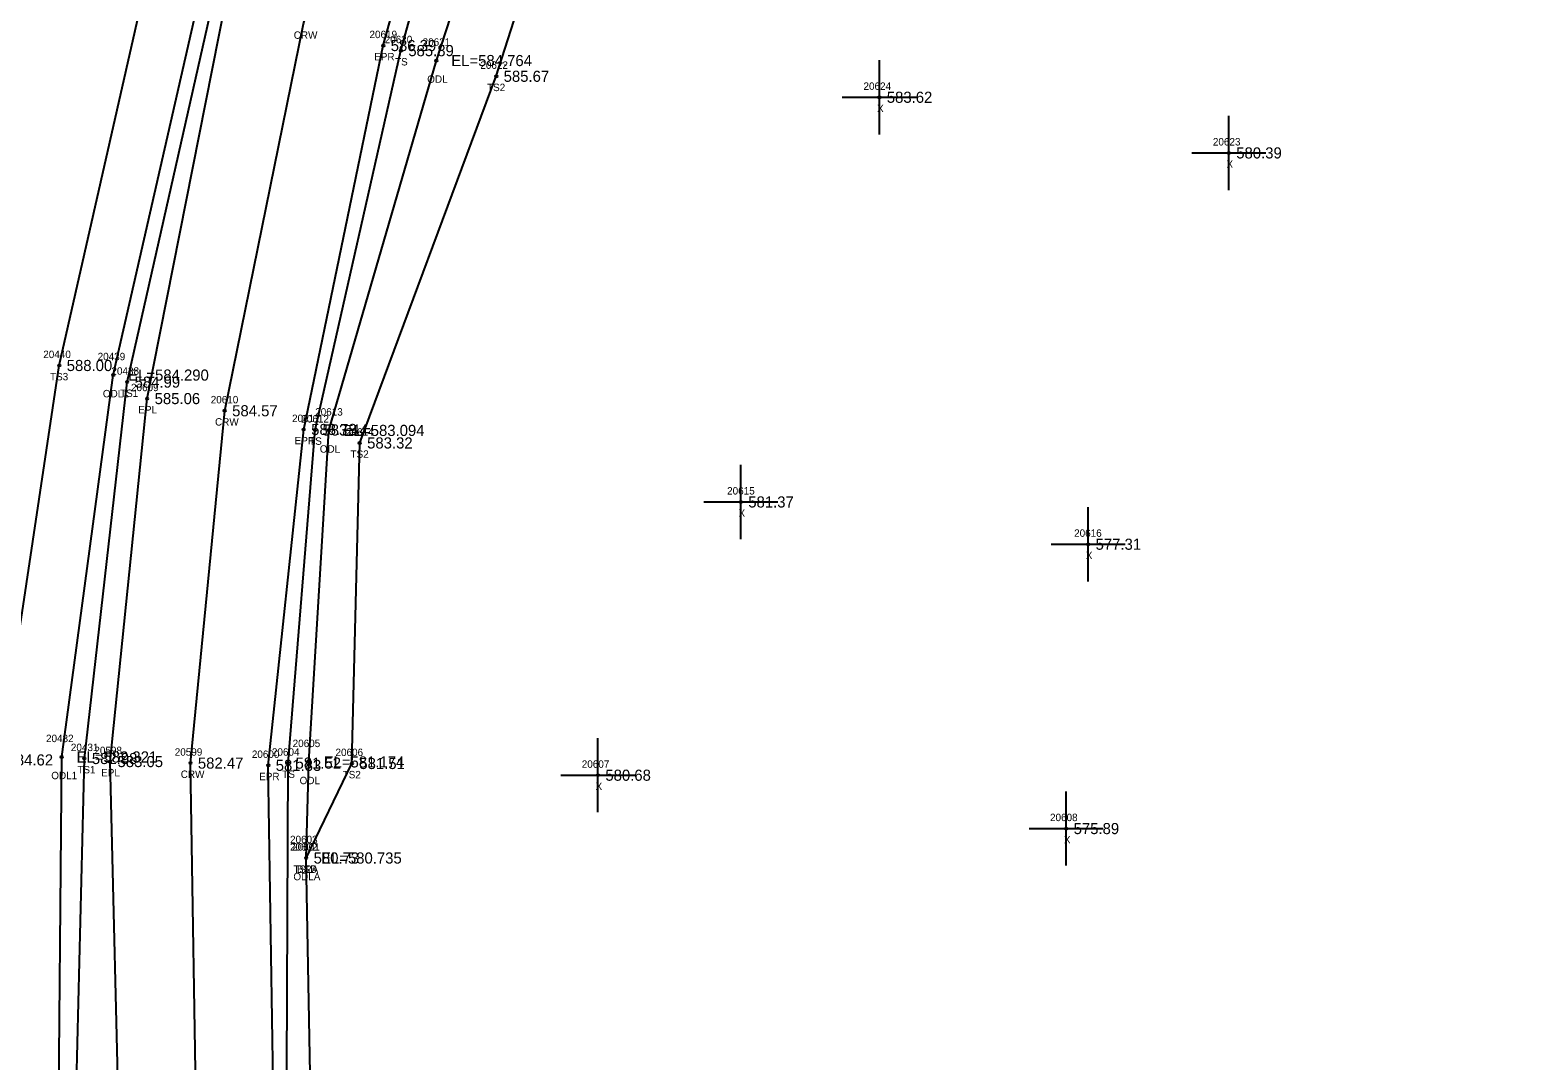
# Model space of a CAD drawing. Extents: x 1695443 to 1696344, y 1087542 to 1090645.
# Drawn here: x 1695695.8 to 1695899, y 1089395 to 1089533.9 of the extents above; entities that cross this region are included whole.
import ezdxf

# ---------------------------------------------------------------- set-up
doc = ezdxf.new("R2010")
doc.units = 0
for name, color, linetype in [('RD_DTM_BkLn1', 7, 'Continuous'), ('RD_DTM_BkLn2', 7, 'Continuous'), ('RD_DTM_BkLn_txCode', 7, 'Continuous'), ('RD_EX_H2O', 7, 'Continuous'), ('RD_EX_H2O_txCode', 7, 'Continuous'), ('RD_EX_Misc', 7, 'Continuous'), ('RD_EX_Misc_txCode', 7, 'Continuous'), ('RD_EX_Road', 7, 'Continuous'), ('RD_EX_Road_txCode', 7, 'Continuous'), ('RD_EX_TX_H2O_ELEV', 7, 'Continuous'), ('RD_EX_TX_Misc_ELEV', 7, 'Continuous'), ('RD_EX_TX_Road_ELEV', 7, 'Continuous'), ('RD_HC_Survey_ELEV', 7, 'Continuous'), ('RD_HC_Survey_txCode', 7, 'Continuous'), ('RD_SMD_Locator', 7, 'Continuous')]:
    doc.layers.add(name, color=color, linetype=linetype)

msp = doc.modelspace()

# ---------------------------------------------------------------- linework, layer by layer
at = {"layer": 'RD_DTM_BkLn1'}
msp.add_lwpolyline([(1695813.78, 1089148.1), (1695785.55, 1089189.03), (1695758.89, 1089235.87), (1695740.64, 1089279.02), (1695725.17, 1089334.02), (1695718.27, 1089382.65), (1695717.41, 1089435.13), (1695722.03, 1089482.62), (1695732.64, 1089534.75), (1695759.85, 1089631.43), (1695787.11, 1089727.89), (1695798.89, 1089774.41), (1695810.31, 1089824.5), (1695818.49, 1089870.61), (1695825.85, 1089922.33), (1695831.69, 1089976.57), (1695835.49, 1090019.27), (1695844.06, 1090117.91), (1695852.56, 1090215.73), (1695861.78, 1090313.02), (1695870.8, 1090411.68), (1695879.44, 1090510.15), (1695888.04, 1090606.94)], dxfattribs=at)
at = {"layer": 'RD_DTM_BkLn2'}
for points in [[(1695696.87, 1089328.65), (1695685.13, 1089358.98), (1695692.41, 1089382.13), (1695691.76, 1089435.56), (1695699.73, 1089488.72), (1695712.17, 1089543.62), (1695742.06, 1089638.06), (1695765.36, 1089733.76), (1695777.86, 1089780.36), (1695790.39, 1089828.61), (1695799.49, 1089874.59), (1695809.45, 1089923.14)], [(1695802.49, 1089139.56), (1695797.31, 1089139.87), (1695796.55, 1089145.92), (1695767.85, 1089172.77), (1695752.08, 1089198.99), (1695743.04, 1089224.25), (1695723.93, 1089271.63), (1695706.46, 1089330), (1695701.78, 1089380.95), (1695703.12, 1089435.75), (1695708.88, 1089486.48), (1695720.72, 1089539.1), (1695747.1, 1089636.56), (1695773.41, 1089730.59), (1695786.04, 1089777.66), (1695796.55, 1089826.24), (1695804.53, 1089873.75), (1695809.45, 1089923.14)], [(1695824.1, 1089156.08), (1695822.08, 1089163.12), (1695799.61, 1089199.21), (1695776.92, 1089245.16), (1695754.8, 1089284.38), (1695737.73, 1089336.15), (1695730.34, 1089383.59), (1695730.57, 1089435.13), (1695734.2, 1089480.03), (1695745.77, 1089531.16), (1695772.55, 1089627.13), (1695801.84, 1089724.13), (1695813.32, 1089771.8), (1695823.97, 1089812.55), (1695828.38, 1089814.06), (1695832.18, 1089812.32)], [(1695733.01, 1089422.34), (1695739.17, 1089435.08), (1695740.22, 1089478.28), (1695758.62, 1089527.7), (1695775.29, 1089579.66), (1695790.54, 1089625.04), (1695813.11, 1089721.69), (1695822.77, 1089769.83), (1695832.18, 1089812.32)], [(1695806.13, 1089128.88), (1695831.97, 1089151.08), (1695836.66, 1089166.87), (1695814.23, 1089210.18), (1695792.32, 1089250.79), (1695765.95, 1089289.34), (1695750.81, 1089305.62), (1695742.03, 1089337.12), (1695733.74, 1089383.59), (1695733.01, 1089422.34)]]:
    msp.add_lwpolyline(points, dxfattribs=at)
at = {"layer": 'RD_EX_H2O'}
for points in [[(1695696.87, 1089328.65), (1695699.57, 1089380.43), (1695700.06, 1089435.96), (1695707.01, 1089487.43), (1695718.96, 1089539.87), (1695744.93, 1089637.33), (1695772.06, 1089731.31), (1695783.6, 1089778.47), (1695794.38, 1089827.05), (1695802.7, 1089874.04), (1695809.45, 1089923.14)], [(1695733.01, 1089422.34), (1695733.36, 1089435.29), (1695736.08, 1089479.97), (1695750.56, 1089529.82), (1695767.47, 1089581.7), (1695784.92, 1089622.19), (1695808.14, 1089722.97), (1695818.49, 1089770.57), (1695827.73, 1089811.05)]]:
    msp.add_lwpolyline(points, dxfattribs=at)
at = {"layer": 'RD_EX_Misc'}
for p, q in [((1695810.26, 1089519.87), (1695810.26, 1089529.87)), ((1695805.26, 1089524.87), (1695815.26, 1089524.87)), ((1695857.36, 1089512.37), (1695857.36, 1089522.37)), ((1695852.36, 1089517.37), (1695862.36, 1089517.37)), ((1695791.59, 1089465.33), (1695791.59, 1089475.33)), ((1695786.59, 1089470.33), (1695796.59, 1089470.33)), ((1695838.4, 1089459.63), (1695838.4, 1089469.63)), ((1695833.4, 1089464.63), (1695843.4, 1089464.63)), ((1695772.33, 1089428.5), (1695772.33, 1089438.5)), ((1695767.33, 1089433.5), (1695777.33, 1089433.5)), ((1695835.44, 1089421.31), (1695835.44, 1089431.31)), ((1695830.44, 1089426.31), (1695840.44, 1089426.31))]:
    msp.add_line(p, q, dxfattribs=at)
at = {"layer": 'RD_EX_Road'}
for points in [[(1695813.78, 1089148.1), (1695805.56, 1089142.08), (1695776.44, 1089183.94), (1695749.27, 1089231.88), (1695730.49, 1089275.72), (1695714.87, 1089332.12), (1695707.87, 1089381.72), (1695706.58, 1089435.34), (1695711.58, 1089484.26), (1695722.15, 1089537.59), (1695749.04, 1089634.88), (1695776.11, 1089730.43), (1695788.13, 1089777.42), (1695798.89, 1089826.76), (1695807.1, 1089870.03), (1695814.71, 1089923.3), (1695820.51, 1089978.16), (1695824.04, 1090019.79), (1695832.76, 1090119.06), (1695841.25, 1090216.76), (1695850.36, 1090314.41), (1695859.24, 1090411.82), (1695868.09, 1090511.63), (1695876.75, 1090608.38)], [(1695728.69, 1089383.6), (1695727.9, 1089434.83), (1695732.68, 1089480.1), (1695743.4, 1089531.84), (1695770.35, 1089628.36), (1695797.63, 1089725.22), (1695809.49, 1089772.37), (1695818.34, 1089811.57), (1695820.65, 1089823.41), (1695822.99, 1089835.26), (1695829.18, 1089869.37), (1695836.32, 1089920.97), (1695842.44, 1089975.46), (1695846.49, 1090018.55), (1695849.32, 1090055.39), (1695850.91, 1090072.92), (1695855.09, 1090117.49), (1695863.53, 1090214.93), (1695872.56, 1090312.44), (1695881.69, 1090410.78), (1695890.45, 1090509.3), (1695899.01, 1090605.4)]]:
    msp.add_lwpolyline(points, dxfattribs=at)
at = {"layer": 'RD_SMD_Locator'}
for centre in [(1695743.4, 1089531.84), (1695745.77, 1089531.16), (1695750.56, 1089529.82), (1695758.62, 1089527.7), (1695810.26, 1089524.87), (1695857.36, 1089517.37), (1695699.73, 1089488.72), (1695707.01, 1089487.43), (1695708.88, 1089486.48), (1695711.58, 1089484.26), (1695722.03, 1089482.62), (1695732.68, 1089480.1), (1695734.2, 1089480.03), (1695736.08, 1089479.97), (1695740.22, 1089478.28), (1695791.59, 1089470.33), (1695838.4, 1089464.63), (1695700.06, 1089435.96), (1695703.12, 1089435.75), (1695706.58, 1089435.34), (1695717.41, 1089435.13), (1695727.9, 1089434.83), (1695730.57, 1089435.13), (1695733.36, 1089435.29), (1695739.17, 1089435.08), (1695772.33, 1089433.5), (1695835.44, 1089426.31), (1695733.01, 1089422.34), (1695733.01, 1089422.34), (1695733.01, 1089422.34)]:
    msp.add_circle(centre, 0.15, dxfattribs=at)

# ---------------------------------------------------------------- texts
at = {"layer": 'RD_DTM_BkLn_txCode'}
for s, p in [('20620', (1695743.59, 1089532.16)), ('TS', (1695744.98, 1089529.16)), ('20622', (1695756.48, 1089528.7)), ('TS2', (1695757.38, 1089525.7)), ('20440', (1695697.57, 1089489.72)), ('TS3', (1695698.48, 1089486.72)), ('20438', (1695706.76, 1089487.48)), ('TS1', (1695707.92, 1089484.48)), ('20612', (1695732.35, 1089481.03)), ('20614', (1695738.37, 1089479.28)), ('TS', (1695733.41, 1089478.03)), ('TS2', (1695738.98, 1089476.28)), ('20431', (1695701.29, 1089436.75)), ('20604', (1695728.39, 1089436.13)), ('20606', (1695736.96, 1089436.08)), ('TS1', (1695702.16, 1089433.75)), ('TS', (1695729.78, 1089433.13)), ('TS2', (1695737.92, 1089433.08)), ('20602', (1695730.83, 1089423.34)), ('20601', (1695731.11, 1089423.34)), ('TS2A', (1695731.28, 1089420.34)), ('BSB', (1695731.76, 1089420.34))]:
    msp.add_text(s, height=1, dxfattribs=at).set_placement(p)
at = {"layer": 'RD_EX_H2O_txCode'}
for s, p in [('20621', (1695748.7, 1089531.82)), ('ODL', (1695749.32, 1089526.82)), ('20439', (1695704.9, 1089489.43)), ('ODL1', (1695705.6, 1089484.43)), ('20613', (1695734.22, 1089481.97)), ('ODL', (1695734.84, 1089476.97)), ('20432', (1695697.94, 1089437.96)), ('20605', (1695731.18, 1089437.29)), ('ODL1', (1695698.65, 1089432.96)), ('ODL', (1695732.12, 1089432.29)), ('20603', (1695730.83, 1089424.34)), ('ODLA', (1695731.28, 1089419.34))]:
    msp.add_text(s, height=1, dxfattribs=at).set_placement(p)
at = {"layer": 'RD_EX_Misc_txCode'}
for s, p in [('20624', (1695808.12, 1089525.87)), ('X', (1695809.95, 1089522.87)), ('20623', (1695855.21, 1089518.37)), ('X', (1695857.04, 1089515.37)), ('20615', (1695789.74, 1089471.33)), ('X', (1695791.28, 1089468.33)), ('20616', (1695836.51, 1089465.63)), ('X', (1695838.08, 1089462.63)), ('20607', (1695770.15, 1089434.5)), ('X', (1695772.01, 1089431.5)), ('20608', (1695833.26, 1089427.31)), ('X', (1695835.13, 1089424.31))]:
    msp.add_text(s, height=1, dxfattribs=at).set_placement(p)
at = {"layer": 'RD_EX_Road_txCode'}
for s, p in [('20619', (1695741.54, 1089532.84)), ('EPR', (1695742.17, 1089529.84)), ('20609', (1695709.4, 1089485.26)), ('EPL', (1695710.38, 1089482.26)), ('20611', (1695731.1, 1089481.1)), ('EPR', (1695731.45, 1089478.1)), ('20598', (1695704.46, 1089436.34)), ('20600', (1695725.68, 1089435.83)), ('EPL', (1695705.37, 1089433.34)), ('EPR', (1695726.67, 1089432.83))]:
    msp.add_text(s, height=1, dxfattribs=at).set_placement(p)
at = {"layer": 'RD_EX_TX_H2O_ELEV'}
for s, p in [('EL=584.764', (1695752.56, 1089529.07)), ('EL=584.290', (1695709.01, 1089486.68)), ('EL=583.094', (1695738.08, 1089479.22)), ('EL=582.321', (1695702.06, 1089435.21)), ('EL=581.174', (1695735.36, 1089434.54)), ('EL=580.735', (1695735.01, 1089421.59))]:
    msp.add_text(s, height=1.5, dxfattribs=at).set_placement(p)
at = {"layer": 'RD_EX_TX_Misc_ELEV'}
for s, p in [('585.89', (1695746.77, 1089530.41)), ('585.67', (1695759.62, 1089526.95)), ('583.62', (1695811.26, 1089524.12)), ('580.39', (1695858.36, 1089516.62)), ('588.00', (1695700.73, 1089487.97)), ('584.99', (1695709.88, 1089485.73)), ('583.44', (1695735.2, 1089479.28)), ('583.32', (1695741.22, 1089477.53)), ('581.37', (1695792.59, 1089469.58)), ('577.31', (1695839.4, 1089463.88)), ('584.62', (1695692.76, 1089434.81)), ('582.98', (1695704.12, 1089435)), ('581.52', (1695731.57, 1089434.38)), ('581.51', (1695740.17, 1089434.33)), ('580.68', (1695773.33, 1089432.75)), ('575.89', (1695836.44, 1089425.56)), ('580.73', (1695734.01, 1089421.59)), ('580.73', (1695734.01, 1089421.59))]:
    msp.add_text(s, height=1.5, dxfattribs=at).set_placement(p)
at = {"layer": 'RD_EX_TX_Road_ELEV'}
for s, p in [('586.39', (1695744.4, 1089531.09)), ('585.06', (1695712.58, 1089483.51)), ('583.78', (1695733.68, 1089479.35)), ('583.05', (1695707.58, 1089434.59)), ('581.83', (1695728.9, 1089434.08))]:
    msp.add_text(s, height=1.5, dxfattribs=at).set_placement(p)
at = {"layer": 'RD_HC_Survey_ELEV'}
for s, p in [('584.57', (1695723.03, 1089481.87)), ('582.47', (1695718.41, 1089434.38))]:
    msp.add_text(s, height=1.5, dxfattribs=at).set_placement(p)
at = {"layer": 'RD_HC_Survey_txCode'}
for s, p in [('CRW', (1695731.33, 1089532.75)), ('20610', (1695720.14, 1089483.62)), ('CRW', (1695720.72, 1089480.62)), ('20599', (1695715.29, 1089436.13)), ('CRW', (1695716.1, 1089433.13))]:
    msp.add_text(s, height=1, dxfattribs=at).set_placement(p)

doc.saveas('drawing.dxf')
